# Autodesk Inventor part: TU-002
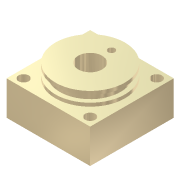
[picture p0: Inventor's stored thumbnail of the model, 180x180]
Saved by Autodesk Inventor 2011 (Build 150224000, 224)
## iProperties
Created: 2008-05
Part Number: TU-002
Document SubType Name: Modeling
Designer: PN
Density: 7.86 g/cm^3
Material: Steel, Mild
Description: Cylinder Head Cover_Front
Mass: 390.492 g
Surface Area: 130.085 cm^2
Volume: 49.681 cm^3
Author: PN
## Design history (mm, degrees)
sketch "Sketch1"
  geometry: L1 (-24.5, 24.5)-(24.5, 24.5); L2 (24.5, 24.5)-(24.5, -24.5); L3 (24.5, -24.5)-(-24.5, -24.5); L4 (-24.5, -24.5)-(-24.5, 24.5); 3 further points
  constraints: 8 end point, 2 midpoint, 2 parallel, 1 horizontal, 1 horizontal alignment, 1 perpendicular, 1 vertical alignment
  dimensions: "Width" = 49 distance of L1.start L1.end; "Height" = 49 distance of L3.end L1.start (= Width)
extrude "Extrusion1" new body sketch "Sketch1" distance "d2" = 20; taper "d3" = 0 deg
sketch "Sketch2"
  geometry: L1 (24.5, 24.5)-(24.5, -24.5) reference; L2 (-24.5, 24.5)-(24.5, 24.5) reference; L3 (-24.5, -24.5)-(-24.5, 24.5) reference; L4 (24.5, -24.5)-(-24.5, -24.5) reference; L5 (19.5, 19.5)-(19.5, -19.5); L6 (19.5, -19.5)-(-19.5, -19.5); L7 (-19.5, -19.5)-(-19.5, 19.5); L8 (-19.5, 19.5)-(19.5, 19.5); 1 further point
  constraints: 8 end point, 3 other
  dimensions: "d4" = 5 distance between parallel lines of L7 L3; "d5" = 39 distance of L5.end L6.end (derived); "d6" = 39 distance of L6.end L7.end (derived)
hole "Hole1" sketch "Sketch2" at (-19.5, -19.5) diameter "d7" = 6; stored, may be unused: countersink angle "d11" = 90 deg, drill point angle "d13" = 118 deg; dims "d8" = 6, "d9" = 4, "d10" = 2, "d12" = 8
pattern_linear "Rectangular Pattern1" dims "d16" = 39 (= d5), "d19" = 39 (= d6)
sketch "Sketch3"
  geometry: L1 (-24.5, 20)-(24.5, 20) reference; L2 (0, 20)-(0, 28); L3 (0, 28)-(20.35, 28); L4 (20.35, 28)-(20.35, 26); L5 (20.35, 26)-(17.8, 26); L6 (17.8, 26)-(17.8, 22); L7 (17.8, 22)-(20.35, 22); L8 (20.35, 22)-(20.35, 20); 1 further point
  constraints: 14 end point, 4 perpendicular, 2 collinear, 2 parallel, 1 midpoint, 1 point on line
  dimensions: "d25" = 8 distance of L2.start L2.end; "d26" = 20.35 distance of L2.end L3.end; "d27" = 2 distance of L3.end L4.end; "d28" = 4 distance of L5.end L6.end; "d29" = 17.8 distance between parallel lines of L6 L2
revolve "Revolution1" sketch "Sketch3" stored, may be unused: angle "d30" = 90 deg
sketch "Sketch4"
  geometry: L1 (0, -20)-(49, -20) reference; L2 (0, 0)-(0, -20) reference; L3 (24.5, -20)-(24.5, -10); 1 further point
  constraints: 2 end point, 1 midpoint, 1 parallel
  dimensions: "d31" = 10 distance of L3.start L3.end
hole "Hole4" sketch "Sketch4" at (24.5, -10) diameter "d48" = 8; stored, may be unused: countersink angle "d52" = 90 deg, drill point angle "d54" = 118 deg; dims "d49" = 9, "d50" = 4, "d51" = 2, "d53" = 14, "d74" = 0.62479, "d75" = 7.985
sketch "Sketch7"
  geometry: L1 (0, 0)-(0, 12.5); C1 r 20.35 at (0, 0) reference; 1 further point
  constraints: 2 end point, 1 coincident, 1 vertical
  dimensions: "d56" = 12.5 distance of L1.start L1.end
hole "Hole5" sketch "Sketch7" at (0, 12.5) diameter "d57" = 4; stored, may be unused: countersink angle "d61" = 90 deg, drill point angle "d63" = 118 deg; dims "d58" = 6, "d59" = 4, "d60" = 2, "d62" = 18
hole "Hole6" diameter "d66" = 14; stored, may be unused: countersink angle "d70" = 90 deg, drill point angle "d72" = 118 deg; dims "d64" = 10, "d65" = 10, "d67" = 6, "d68" = 4, "d69" = 2, "d71" = 14
workplane "Work Plane4"
body "Solid1"
other parameters: "d73" = 24
